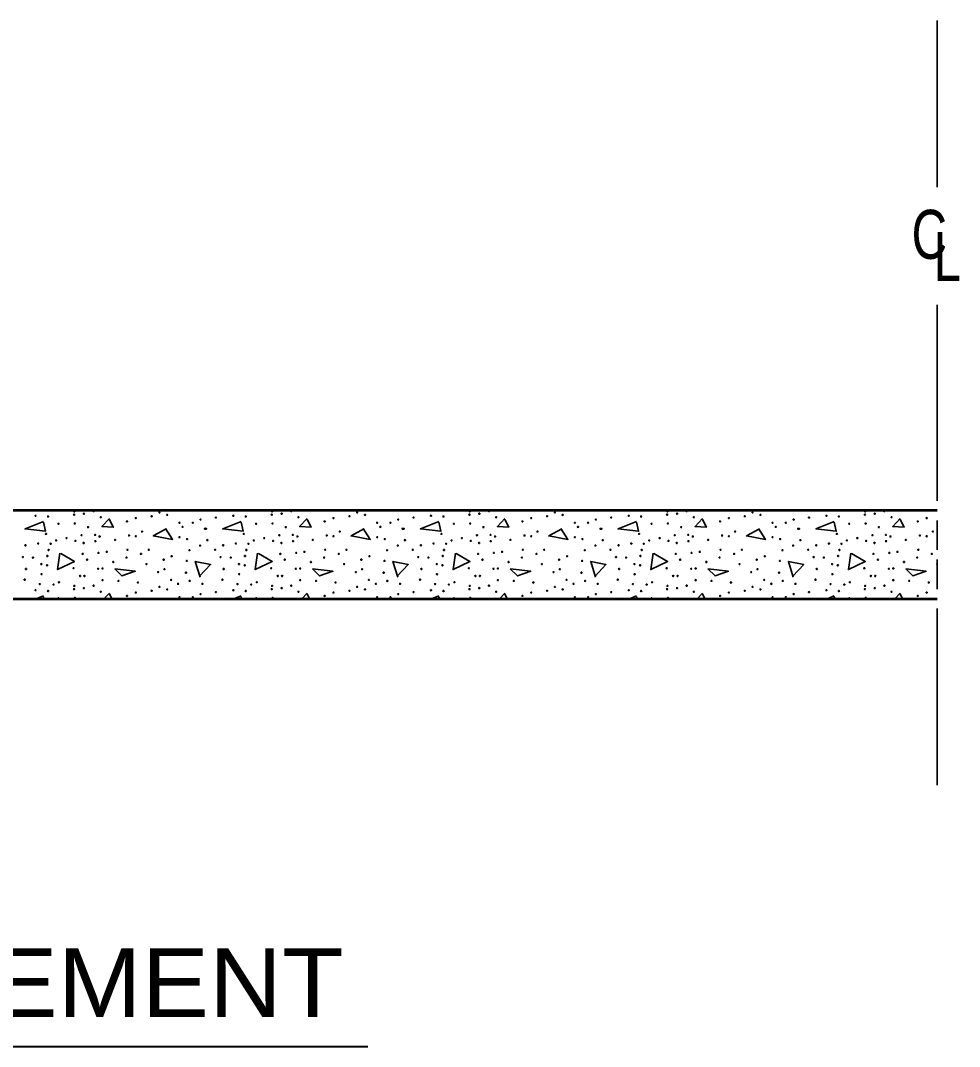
# Model space of a CAD drawing. Extents: x -54 to 626, y -41 to 399.
# Drawn here: x 116.9 to 164.7, y 192.7 to 245 of the extents above; entities that cross this region are included whole.
import ezdxf
from ezdxf.enums import TextEntityAlignment as Align

# ---------------------------------------------------------------- set-up
doc = ezdxf.new("R2010")
doc.units = 0
doc.header["$LTSCALE"] = 0.9
doc.layers.add('1', color=7, linetype='Continuous', lineweight=35)

msp = doc.modelspace()

# ---------------------------------------------------------------- linework, layer by layer
at = {"layer": '1'}
for p, q in [((163.6023, 236.5399), (163.6023, 245.0399)), ((163.6023, 220.5399), (163.6023, 230.5399)), ((163.6023, 219.5399), (163.6023, 218.0399)), ((163.6023, 217.5399), (163.6023, 216.0399)), ((118.0397, 215.6893), (117.6702, 215.5399)), ((118.0635, 215.5399), (118.0397, 215.6493)), ((121.3997, 215.8293), (121.1248, 215.5399)), ((121.5244, 215.5399), (121.3997, 215.7893)), ((128.1197, 215.6893), (127.7502, 215.5399)), ((128.1435, 215.5399), (128.1197, 215.6493)), ((131.4797, 215.8293), (131.2048, 215.5399)), ((131.6044, 215.5399), (131.4797, 215.7893)), ((138.1997, 215.6893), (137.8302, 215.5399)), ((138.2235, 215.5399), (138.1997, 215.6493)), ((141.5598, 215.8293), (141.2848, 215.5399)), ((141.6844, 215.5399), (141.5598, 215.7893)), ((148.2798, 215.6893), (147.9102, 215.5399)), ((148.3035, 215.5399), (148.2798, 215.6493)), ((151.6397, 215.8293), (151.3648, 215.5399)), ((151.7644, 215.5399), (151.6397, 215.7893)), ((158.3597, 215.6893), (157.9902, 215.5399)), ((158.3835, 215.5399), (158.3597, 215.6493)), ((161.7198, 215.8293), (161.4448, 215.5399)), ((161.8444, 215.5399), (161.7198, 215.7893)), ((163.6023, 215.0399), (163.6023, 206.0399))]:
    msp.add_line(p, q, dxfattribs=at)
at = {"layer": '1', "lineweight": 40}
msp.add_line((66.5198, 192.7051), (134.58, 192.7051), dxfattribs=at)
at = {"layer": '1', "lineweight": 53}
msp.add_lwpolyline([(163.6023, 220.0399), (92.1023, 220.0399), (92.1023, 218.0396), (92.1023, 215.5399), (163.6023, 215.5399)], dxfattribs=at)
at = {"layer": '1'}
for points in [[(118.0397, 219.4893), (117.0998, 219.1093), (118.1397, 218.9893), (118.0397, 219.4493)], [(121.3997, 219.6293), (121.0198, 219.2293), (121.5998, 219.1893), (121.3997, 219.5893)], [(128.1197, 219.4893), (127.1797, 219.1093), (128.2198, 218.9893), (128.1197, 219.4493)], [(131.4797, 219.6293), (131.0998, 219.2293), (131.6797, 219.1893), (131.4797, 219.5893)], [(138.1997, 219.4893), (137.2597, 219.1093), (138.2997, 218.9893), (138.1997, 219.4493)], [(141.5598, 219.6293), (141.1797, 219.2293), (141.7597, 219.1893), (141.5598, 219.5893)], [(148.2798, 219.4893), (147.3397, 219.1093), (148.3798, 218.9893), (148.2798, 219.4493)], [(151.6397, 219.6293), (151.2597, 219.2293), (151.8397, 219.1893), (151.6397, 219.5893)], [(158.3597, 219.4893), (157.4197, 219.1093), (158.4597, 218.9893), (158.3597, 219.4493)], [(161.7198, 219.6293), (161.3397, 219.2293), (161.9197, 219.1893), (161.7198, 219.5893)], [(124.2997, 219.1093), (123.6397, 218.7493), (124.6197, 218.5693), (124.2597, 219.1293)], [(134.3798, 219.1093), (133.7198, 218.7493), (134.6997, 218.5693), (134.3398, 219.1293)], [(144.4597, 219.1093), (143.7997, 218.7493), (144.7798, 218.5693), (144.4197, 219.1293)], [(154.5397, 219.1093), (153.8798, 218.7493), (154.8597, 218.5693), (154.4998, 219.1293)], [(118.9197, 217.8493), (119.6197, 217.4493), (118.7597, 217.0293), (118.8798, 217.8693)], [(128.9998, 217.8493), (129.6997, 217.4493), (128.8398, 217.0293), (128.9597, 217.8693)], [(139.0797, 217.8493), (139.7798, 217.4493), (138.9197, 217.0293), (139.0397, 217.8693)], [(149.1598, 217.8493), (149.8597, 217.4493), (148.9998, 217.0293), (149.1197, 217.8693)], [(159.2397, 217.8493), (159.9398, 217.4493), (159.0797, 217.0293), (159.1997, 217.8693)], [(126.0198, 216.6493), (125.7797, 217.4493), (126.5597, 217.2893), (125.9997, 216.6893)], [(136.0998, 216.6493), (135.8597, 217.4493), (136.6397, 217.2893), (136.0797, 216.6893)], [(146.1797, 216.6493), (145.9398, 217.4493), (146.7198, 217.2893), (146.1598, 216.6893)], [(156.2597, 216.6493), (156.0197, 217.4493), (156.7997, 217.2893), (156.2397, 216.6893)]]:
    msp.add_lwpolyline(points, dxfattribs=at)
for points in [[(121.6797, 217.0693), (122.7197, 216.9493), (122.0397, 216.7093)], [(131.7597, 217.0693), (132.7997, 216.9493), (132.1197, 216.7093)], [(141.8398, 217.0693), (142.8798, 216.9493), (142.1997, 216.7093)], [(151.9197, 217.0693), (152.9597, 216.9493), (152.2798, 216.7093)], [(161.9998, 217.0693), (163.0397, 216.9493), (162.3597, 216.7093)]]:
    msp.add_lwpolyline(points, close=True, dxfattribs=at)
for centre in [(119.5992, 219.8324), (119.6125, 219.9999), (120.1028, 219.8854), (120.5932, 220.0131), (123.9539, 219.9469), (124.3515, 219.8191), (129.6792, 219.8324), (129.6925, 219.9999), (130.1828, 219.8854), (130.6732, 220.0131), (134.0339, 219.9469), (134.4315, 219.8191), (139.7592, 219.8324), (139.7725, 219.9999), (140.2628, 219.8854), (140.7532, 220.0131), (144.1139, 219.9469), (144.5115, 219.8191), (149.8392, 219.8324), (149.8525, 219.9999), (150.3428, 219.8854), (150.8332, 220.0131), (154.1939, 219.9469), (154.5915, 219.8191), (159.9192, 219.8324), (159.9325, 219.9999), (160.4228, 219.8854), (160.9132, 220.0131), (117.6378, 219.7794), (118.2739, 219.7395), (118.804, 219.3683), (119.639, 219.3816), (120.9587, 219.6998), (122.2972, 219.4877), (122.7479, 219.66), (123.5563, 219.7528), (124.9743, 219.4214), (125.6503, 219.4214), (126.0479, 219.5805), (126.8298, 219.6865), (127.7178, 219.7794), (128.3539, 219.7395), (128.884, 219.3683), (129.719, 219.3816), (131.0387, 219.6998), (132.3772, 219.4877), (132.8279, 219.66), (133.6363, 219.7528), (135.0543, 219.4214), (135.7303, 219.4214), (136.1279, 219.5805), (136.9098, 219.6865), (137.7978, 219.7794), (138.4339, 219.7395), (138.964, 219.3683), (139.799, 219.3816), (141.1187, 219.6998), (142.4572, 219.4877), (142.9079, 219.66), (143.7163, 219.7528), (145.1343, 219.4214), (145.8103, 219.4214), (146.2079, 219.5805), (146.9898, 219.6865), (147.8778, 219.7794), (148.5139, 219.7395), (149.044, 219.3683), (149.879, 219.3816), (151.1987, 219.6998), (152.5372, 219.4877), (152.9879, 219.66), (153.7963, 219.7528), (155.2143, 219.4214), (155.8903, 219.4214), (156.2879, 219.5805), (157.0698, 219.6865), (157.9578, 219.7794), (158.5939, 219.7395), (159.124, 219.3683), (159.959, 219.3816), (161.2787, 219.6998), (162.6172, 219.4877), (163.0679, 219.66), (118.1679, 218.8513), (119.9835, 218.785), (120.3149, 219.1961), (120.6728, 218.7983), (122.4032, 218.7718), (123.0659, 218.9707), (125.1334, 219.2092), (126.2732, 219.1165), (126.3262, 219.1165), (128.2479, 218.8513), (130.0635, 218.785), (130.3949, 219.1961), (130.7528, 218.7983), (132.4832, 218.7718), (133.1459, 218.9707), (135.2134, 219.2092), (136.3532, 219.1165), (136.4062, 219.1165), (138.3279, 218.8513), (140.1435, 218.785), (140.4749, 219.1961), (140.8328, 218.7983), (142.5632, 218.7718), (143.2259, 218.9707), (145.2934, 219.2092), (146.4332, 219.1165), (146.4862, 219.1165), (148.4079, 218.8513), (150.2235, 218.785), (150.5549, 219.1961), (150.9128, 218.7983), (152.6432, 218.7718), (153.3059, 218.9707), (155.3734, 219.2092), (156.5132, 219.1165), (156.5662, 219.1165), (158.4879, 218.8513), (160.3035, 218.785), (160.6349, 219.1961), (160.9928, 218.7983), (162.7232, 218.7718), (163.3859, 218.9707), (117.1209, 218.268), (117.7703, 218.3608), (118.4064, 218.3476), (118.6847, 218.5199), (119.2149, 218.6392), (119.6655, 218.4934), (120.0896, 218.3873), (120.6859, 218.4801), (120.9057, 218.7188), (121.6876, 218.5464), (122.7479, 218.732), (124.9744, 218.679), (125.3587, 218.5862), (126.0214, 218.2548), (126.3925, 218.5331), (127.2009, 218.268), (127.8503, 218.3608), (128.4864, 218.3476), (128.7647, 218.5199), (129.2949, 218.6392), (129.7455, 218.4934), (130.1696, 218.3873), (130.7659, 218.4801), (130.9857, 218.7188), (131.7676, 218.5464), (132.8279, 218.732), (135.0544, 218.679), (135.4387, 218.5862), (136.1014, 218.2548), (136.4725, 218.5331), (137.2809, 218.268), (137.9303, 218.3608), (138.5664, 218.3476), (138.8447, 218.5199), (139.3749, 218.6392), (139.8255, 218.4934), (140.2496, 218.3873), (140.8459, 218.4801), (141.0657, 218.7188), (141.8476, 218.5464), (142.9079, 218.732), (145.1344, 218.679), (145.5187, 218.5862), (146.1814, 218.2548), (146.5525, 218.5331), (147.3609, 218.268), (148.0103, 218.3608), (148.6464, 218.3476), (148.9247, 218.5199), (149.4549, 218.6392), (149.9055, 218.4934), (150.3296, 218.3873), (150.9259, 218.4801), (151.1457, 218.7188), (151.9276, 218.5464), (152.9879, 218.732), (155.2144, 218.679), (155.5987, 218.5862), (156.2614, 218.2548), (156.6325, 218.5331), (157.4409, 218.268), (158.0903, 218.3608), (158.7264, 218.3476), (159.0047, 218.5199), (159.5349, 218.6392), (159.9855, 218.4934), (160.4096, 218.3873), (161.0059, 218.4801), (161.2257, 218.7188), (162.0076, 218.5464), (163.0679, 218.732), (118.2342, 217.7245), (118.3004, 218.0294), (120.0365, 217.8306), (120.845, 217.8836), (121.2634, 217.9366), (122.3237, 218.0427), (123.0129, 217.8306), (123.4105, 218.0427), (124.5767, 217.7112), (125.478, 218.0161), (126.7901, 218.0427), (128.3142, 217.7245), (128.3804, 218.0294), (130.1165, 217.8306), (130.925, 217.8836), (131.3434, 217.9366), (132.4037, 218.0427), (133.0929, 217.8306), (133.4905, 218.0427), (134.6567, 217.7112), (135.558, 218.0161), (136.8701, 218.0427), (138.3942, 217.7245), (138.4604, 218.0294), (140.1965, 217.8306), (141.005, 217.8836), (141.4234, 217.9366), (142.4837, 218.0427), (143.1729, 217.8306), (143.5705, 218.0427), (144.7367, 217.7112), (145.638, 218.0161), (146.9501, 218.0427), (148.4742, 217.7245), (148.5404, 218.0294), (150.2765, 217.8306), (151.085, 217.8836), (151.5034, 217.9366), (152.5637, 218.0427), (153.2529, 217.8306), (153.6505, 218.0427), (154.8167, 217.7112), (155.718, 218.0161), (157.0301, 218.0427), (158.5542, 217.7245), (158.6204, 218.0294), (160.3565, 217.8306), (161.165, 217.8836), (161.5834, 217.9366), (162.6437, 218.0427), (163.3329, 217.8306), (116.9883, 217.6715), (117.5052, 217.6449), (117.9293, 217.3134), (118.2209, 217.2472), (120.2619, 217.5388), (121.5948, 217.4195), (122.2708, 217.6449), (123.2912, 217.3134), (124.1659, 217.5388), (125.3454, 217.4725), (127.0683, 217.6715), (127.5852, 217.6449), (128.0093, 217.3134), (128.3009, 217.2472), (130.3419, 217.5388), (131.6748, 217.4195), (132.3508, 217.6449), (133.3712, 217.3134), (134.2459, 217.5388), (135.4254, 217.4725), (137.1483, 217.6715), (137.6652, 217.6449), (138.0893, 217.3134), (138.3809, 217.2472), (140.4219, 217.5388), (141.7548, 217.4195), (142.4308, 217.6449), (143.4512, 217.3134), (144.3259, 217.5388), (145.5054, 217.4725), (147.2283, 217.6715), (147.7452, 217.6449), (148.1693, 217.3134), (148.4609, 217.2472), (150.5019, 217.5388), (151.8348, 217.4195), (152.5108, 217.6449), (153.5312, 217.3134), (154.4059, 217.5388), (155.5854, 217.4725), (157.3083, 217.6715), (157.8252, 217.6449), (158.2493, 217.3134), (158.5409, 217.2472), (160.5819, 217.5388), (161.9148, 217.4195), (162.5908, 217.6449), (117.1474, 217.0616), (117.9426, 216.7964), (119.5727, 217.1013), (119.9041, 216.7036), (120.1294, 216.7036), (120.8253, 217.0726), (121.0514, 217.0882), (123.8876, 216.9025), (124.2057, 217.0483), (125.3057, 216.876), (127.2274, 217.0616), (128.0226, 216.7964), (129.6527, 217.1013), (129.9841, 216.7036), (130.2094, 216.7036), (130.9053, 217.0726), (131.1314, 217.0882), (133.9676, 216.9025), (134.2857, 217.0483), (135.3857, 216.876), (137.3074, 217.0616), (138.1026, 216.7964), (139.7327, 217.1013), (140.0641, 216.7036), (140.2894, 216.7036), (140.9853, 217.0726), (141.2114, 217.0882), (144.0476, 216.9025), (144.3657, 217.0483), (145.4657, 216.876), (147.3874, 217.0616), (148.1826, 216.7964), (149.8127, 217.1013), (150.1441, 216.7036), (150.3694, 216.7036), (151.0653, 217.0726), (151.2914, 217.0882), (154.1276, 216.9025), (154.4457, 217.0483), (155.5457, 216.876), (157.4674, 217.0616), (158.2626, 216.7964), (159.8927, 217.1013), (160.2241, 216.7036), (160.4494, 216.7036), (161.1453, 217.0726), (161.3714, 217.0882), (117.0812, 216.5181), (117.8499, 216.2927), (118.5523, 216.2661), (118.8306, 216.3854), (119.6125, 216.1999), (120.5932, 216.2131), (121.0514, 216.4915), (121.8599, 216.4518), (122.8539, 216.3722), (123.9539, 216.1469), (124.5503, 216.5048), (124.9081, 216.3059), (125.4912, 216.4518), (126.1407, 216.3059), (127.1612, 216.5181), (127.9299, 216.2927), (128.6323, 216.2661), (128.9106, 216.3854), (129.6925, 216.1999), (130.6732, 216.2131), (131.1314, 216.4915), (131.9399, 216.4518), (132.9339, 216.3722), (134.0339, 216.1469), (134.6303, 216.5048), (134.9881, 216.3059), (135.5712, 216.4518), (136.2207, 216.3059), (137.2412, 216.5181), (138.0099, 216.2927), (138.7123, 216.2661), (138.9906, 216.3854), (139.7725, 216.1999), (140.7532, 216.2131), (141.2114, 216.4915), (142.0199, 216.4518), (143.0139, 216.3722), (144.1139, 216.1469), (144.7103, 216.5048), (145.0681, 216.3059), (145.6512, 216.4518), (146.3007, 216.3059), (147.3212, 216.5181), (148.0899, 216.2927), (148.7923, 216.2661), (149.0706, 216.3854), (149.8525, 216.1999), (150.8332, 216.2131), (151.2914, 216.4915), (152.0999, 216.4518), (153.0939, 216.3722), (154.1939, 216.1469), (154.7903, 216.5048), (155.1481, 216.3059), (155.7312, 216.4518), (156.3807, 216.3059), (157.4012, 216.5181), (158.1699, 216.2927), (158.8723, 216.2661), (159.1506, 216.3854), (159.9325, 216.1999), (160.9132, 216.2131), (161.3714, 216.4915), (162.1799, 216.4518), (163.1739, 216.3722), (117.6378, 215.9794), (118.2739, 215.9395), (119.5992, 216.0324), (120.1028, 216.0854), (120.9587, 215.8998), (122.2972, 215.6877), (122.7479, 215.86), (123.5563, 215.9528), (124.3515, 216.0191), (124.9743, 215.6214), (125.6503, 215.6214), (126.0479, 215.7805), (126.8298, 215.8865), (127.7178, 215.9794), (128.3539, 215.9395), (129.6792, 216.0324), (130.1828, 216.0854), (131.0387, 215.8998), (132.3772, 215.6877), (132.8279, 215.86), (133.6363, 215.9528), (134.4315, 216.0191), (135.0543, 215.6214), (135.7303, 215.6214), (136.1279, 215.7805), (136.9098, 215.8865), (137.7978, 215.9794), (138.4339, 215.9395), (139.7592, 216.0324), (140.2628, 216.0854), (141.1187, 215.8998), (142.4572, 215.6877), (142.9079, 215.86), (143.7163, 215.9528), (144.5115, 216.0191), (145.1343, 215.6214), (145.8103, 215.6214), (146.2079, 215.7805), (146.9898, 215.8865), (147.8778, 215.9794), (148.5139, 215.9395), (149.8392, 216.0324), (150.3428, 216.0854), (151.1987, 215.8998), (152.5372, 215.6877), (152.9879, 215.86), (153.7963, 215.9528), (154.5915, 216.0191), (155.2143, 215.6214), (155.8903, 215.6214), (156.2879, 215.7805), (157.0698, 215.8865), (157.9578, 215.9794), (158.5939, 215.9395), (159.9192, 216.0324), (160.4228, 216.0854), (161.2787, 215.8998), (162.6172, 215.6877), (163.0679, 215.86), (118.804, 215.5683), (119.639, 215.5816), (128.884, 215.5683), (129.719, 215.5816), (138.964, 215.5683), (139.799, 215.5816), (149.044, 215.5683), (149.879, 215.5816), (159.124, 215.5683), (159.959, 215.5816)]:
    msp.add_circle(centre, 0.0265, dxfattribs=at)
for centre, start, end in [((118.5523, 220.0661), 262.28656, 277.71344), ((128.6323, 220.0661), 262.28656, 277.71344), ((138.7123, 220.0661), 262.28656, 277.71344), ((148.7923, 220.0661), 262.28656, 277.71344), ((158.8723, 220.0661), 262.28656, 277.71344), ((163.6112, 217.3134), 109.58284, 250.41716)]:
    msp.add_arc(centre, 0.0265, start, end, dxfattribs=at)

# ---------------------------------------------------------------- texts
at = {"layer": '1', "width": 0.75}
for s, p in [('C', (162.3, 232.8822)), ('L', (163.4308, 231.751))]:
    msp.add_text(s, height=2.5, dxfattribs=at).set_placement(p)
at = {"layer": '1', "width": 1.1}
msp.add_text('DELINEATOR PLACEMENT', height=3.5, dxfattribs=at).set_placement((100.4449, 194.2051), align=Align.CENTER)

doc.saveas('drawing.dxf')
